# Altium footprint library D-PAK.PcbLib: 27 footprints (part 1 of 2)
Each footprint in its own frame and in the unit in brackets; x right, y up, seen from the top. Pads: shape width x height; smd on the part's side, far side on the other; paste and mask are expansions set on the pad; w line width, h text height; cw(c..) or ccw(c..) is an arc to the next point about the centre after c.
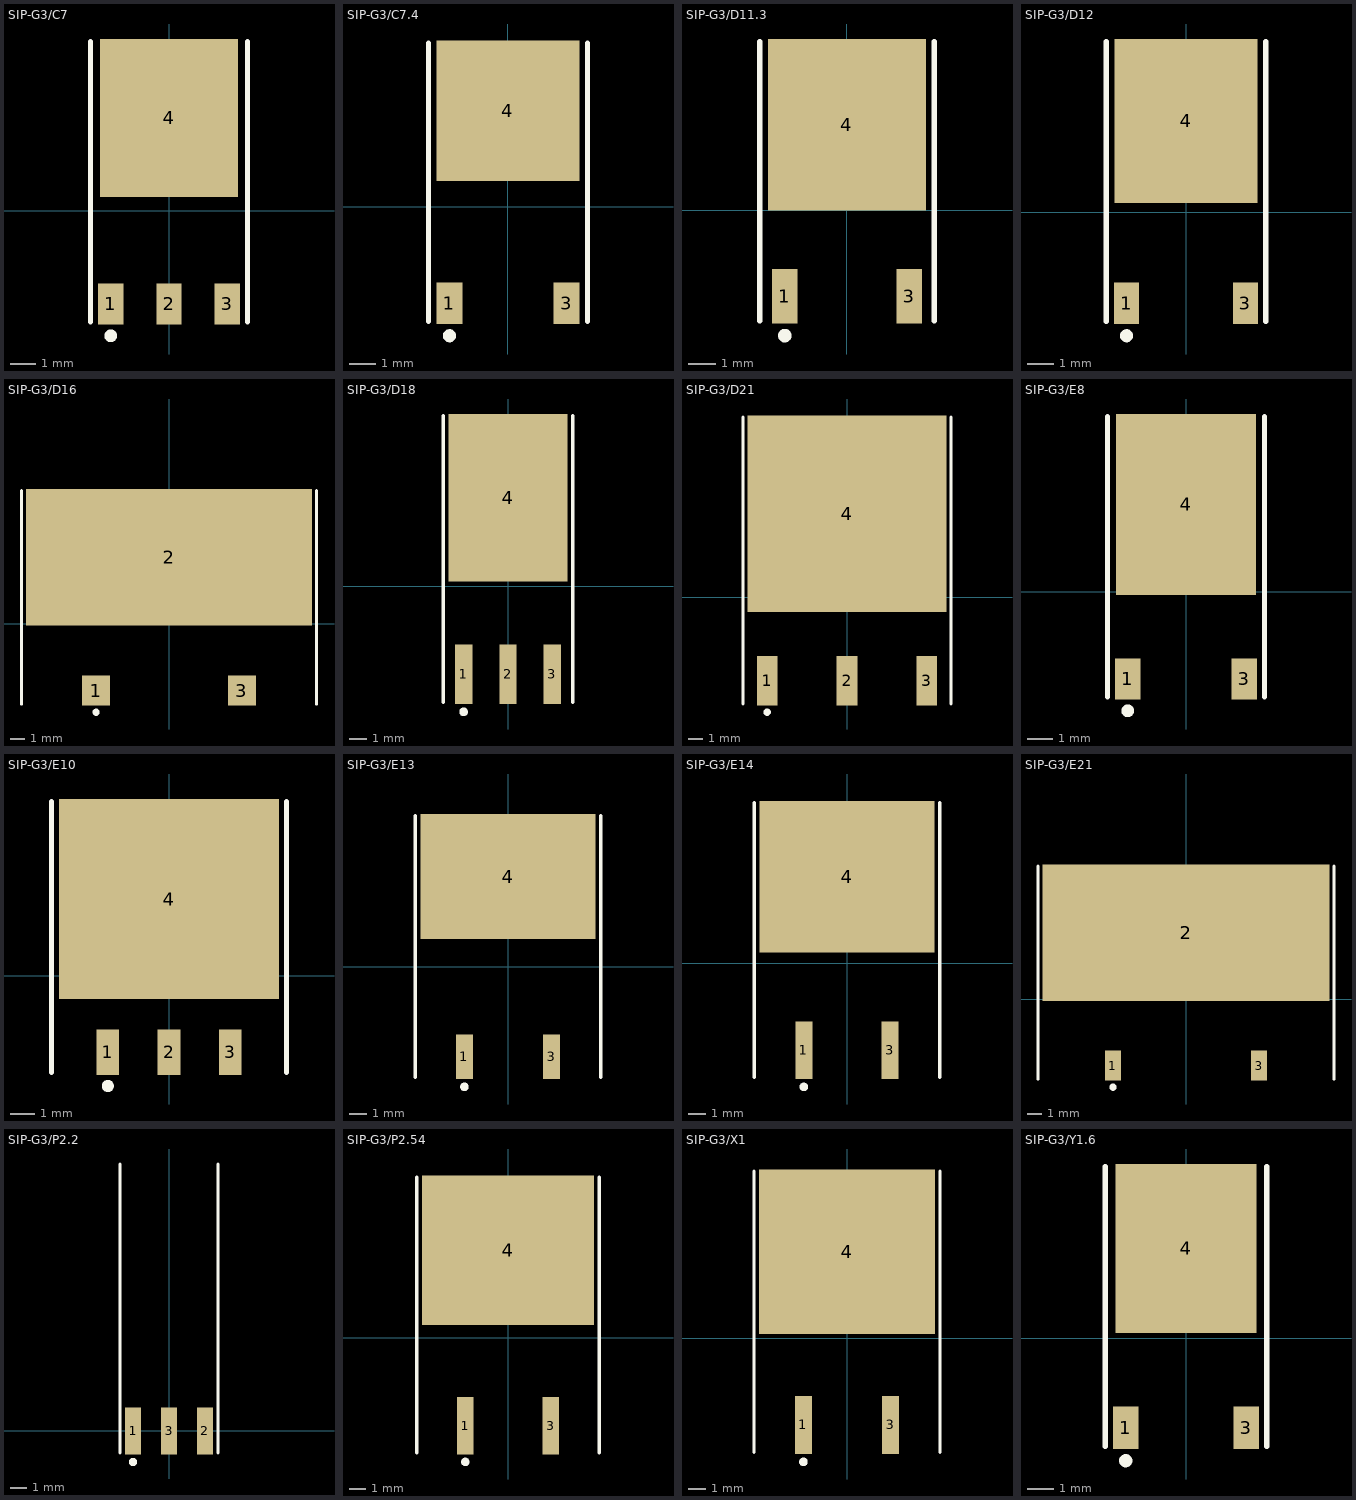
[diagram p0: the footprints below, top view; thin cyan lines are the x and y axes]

## SIP-G3/C7 [mm]
pads (4):
  rect 1x1.6 smd: 1(-2.285,-3.65) 2(0,-3.65) 3(2.285,-3.65)
  rect 5.4x6.2 smd: 4(0,3.65)
Top Overlay:
  circle w0.25: c-2.285,-4.9 r0.125
  lines w0.2: -3.085,-4.35 -3.085,6.65 ; 3.085,-4.35 3.085,6.65

## SIP-G3/C7.4 [mm]
pads (3):
  rect 1x1.6 smd: 1(-2.25,-3.7) 3(2.25,-3.7)
  rect 5.5x5.4 smd: 4(0,3.7)
Top Overlay:
  circle w0.25: c-2.25,-4.95 r0.125
  lines w0.2: -3.05,-4.4 -3.05,6.3 ; 3.05,-4.4 3.05,6.3

## SIP-G3/D11.3 [mm]
pads (3):
  rect 0.95x2 smd: 1(-2.285,-3.15) 3(2.285,-3.15)
  rect 5.8x6.3 smd: 4(0,3.15)
Top Overlay:
  circle w0.25: c-2.285,-4.6 r0.125
  lines w0.2: -3.2,-4.05 -3.2,6.2 ; 3.2,-4.05 3.2,6.2

## SIP-G3/D12 [mm]
pads (3):
  rect 0.95x1.6 smd: 1(-2.285,-3.5) 3(2.285,-3.5)
  rect 5.5x6.3 smd: 4(0,3.5)
Top Overlay:
  circle w0.25: c-2.285,-4.75 r0.125
  lines w0.2: -3.06,-4.2 -3.06,6.55 ; 3.06,-4.2 3.06,6.55

## SIP-G3/D16 [mm]
pads (3):
  rect 1.95x2.1 smd: 1(-5.08,-4.65) 3(5.08,-4.65)
  rect 19.95x9.5 smd: 2(0,4.65)
Top Overlay:
  circle w0.25: c-5.08,-6.15 r0.125
  lines w0.2: -10.275,-5.6 -10.275,9.3 ; 10.275,-5.6 10.275,9.3

## SIP-G3/D18 [mm]
pads (4):
  rect 1x3.4 smd: 1(-2.54,-5.05) 2(0,-5.05) 3(2.54,-5.05)
  rect 6.8x9.6 smd: 4(0,5.05)
Top Overlay:
  circle w0.25: c-2.54,-7.2 r0.125
  lines w0.2: -3.7,-6.65 -3.7,9.75 ; 3.7,-6.65 3.7,9.75

## SIP-G3/D21 [mm]
pads (4):
  rect 1.4x3.4 smd: 1(-5.45,-5.7) 2(0,-5.7) 3(5.45,-5.7)
  rect 13.6x13.4 smd: 4(0,5.7)
Top Overlay:
  circle w0.25: c-5.45,-7.85 r0.125
  lines w0.2: -7.1,-7.3 -7.1,12.3 ; 7.1,-7.3 7.1,12.3

## SIP-G3/E8 [mm]
pads (3):
  rect 1x1.6 smd: 1(-2.285,-3.425) 3(2.285,-3.425)
  rect 5.5x7.1 smd: 4(0,3.425)
Top Overlay:
  circle w0.25: c-2.285,-4.675 r0.125
  lines w0.2: -3.085,-4.125 -3.085,6.875 ; 3.085,-4.125 3.085,6.875

## SIP-G3/E10 [mm]
pads (4):
  rect 0.95x1.9 smd: 1(-2.54,-3.175) 2(0,-3.175) 3(2.54,-3.175)
  rect 9.15x8.3 smd: 4(0,3.175)
Top Overlay:
  circle w0.25: c-2.54,-4.575 r0.125
  lines w0.2: -4.875,-4.025 -4.875,7.225 ; 4.875,-4.025 4.875,7.225

## SIP-G3/E13 [mm]
pads (3):
  rect 1x2.6 smd: 1(-2.54,-5.25) 3(2.54,-5.25)
  rect 10.2x7.3 smd: 4(0,5.25)
Top Overlay:
  circle w0.25: c-2.54,-7 r0.125
  lines w0.2: -5.4,-6.45 -5.4,8.8 ; 5.4,-6.45 5.4,8.8

## SIP-G3/E14 [mm]
pads (3):
  rect 1x3.4 smd: 1(-2.54,-5.1) 3(2.54,-5.1)
  rect 10.3x8.9 smd: 4(0,5.1)
Top Overlay:
  circle w0.25: c-2.54,-7.25 r0.125
  lines w0.2: -5.45,-6.7 -5.45,9.45 ; 5.45,-6.7 5.45,9.45

## SIP-G3/E21 [mm]
pads (3):
  rect 1.1x2.1 smd: 1(-5.08,-4.625) 3(5.08,-4.625)
  rect 20x9.5 smd: 2(0,4.625)
Top Overlay:
  circle w0.25: c-5.08,-6.125 r0.125
  lines w0.2: -10.3,-5.575 -10.3,9.275 ; 10.3,-5.575 10.3,9.275

## SIP-G3/P2.2 [mm]
pads (3):
  rect 1x2.9 smd: 1(-2.2,0) 2(2.2,0) 3(0,0)
Top Overlay:
  circle w0.25: c-2.2,-1.9 r0.125
  lines w0.2: -3,-1.35 -3,16.35 ; 3,-1.35 3,16.35

## SIP-G3/P2.54 [mm]
pads (3):
  rect 1x3.4 smd: 1(-2.54,-5.225) 3(2.54,-5.225)
  rect 10.25x8.9 smd: 4(0,5.225)
Top Overlay:
  circle w0.25: c-2.54,-7.375 r0.125
  lines w0.2: -5.425,-6.825 -5.425,9.575 ; 5.425,-6.825 5.425,9.575

## SIP-G3/X1 [mm]
pads (3):
  rect 1x3.4 smd: 1(-2.54,-5.05) 3(2.54,-5.05)
  rect 10.25x9.6 smd: 4(0,5.05)
Top Overlay:
  circle w0.25: c-2.54,-7.2 r0.125
  lines w0.2: -5.425,-6.65 -5.425,9.75 ; 5.425,-6.65 5.425,9.75

## SIP-G3/Y1.6 [mm]
pads (3):
  rect 0.95x1.6 smd: 1(-2.285,-3.4) 3(2.285,-3.4)
  rect 5.35x6.4 smd: 4(0,3.4)
Top Overlay:
  circle w0.25: c-2.285,-4.65 r0.125
  lines w0.2: -3.06,-4.1 -3.06,6.5 ; 3.06,-4.1 3.06,6.5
